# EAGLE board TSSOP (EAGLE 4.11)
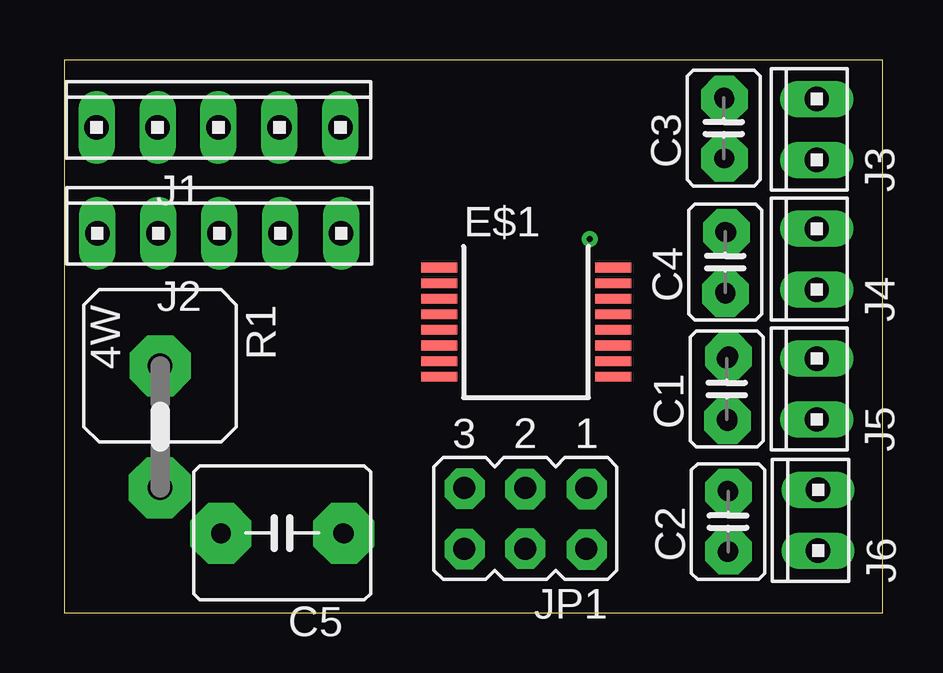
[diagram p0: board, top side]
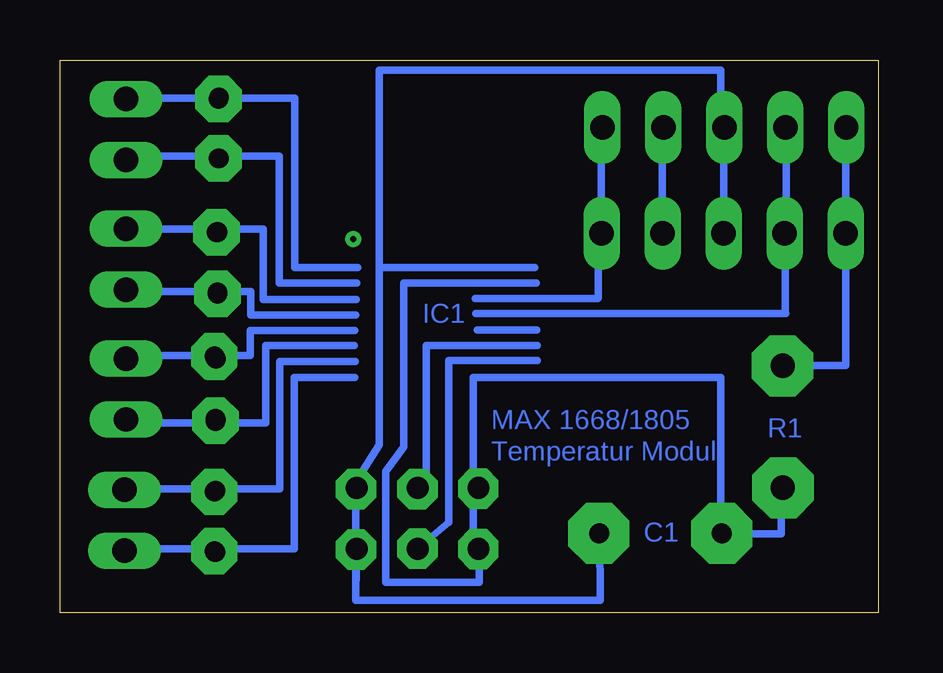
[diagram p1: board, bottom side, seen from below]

Size 34.1 x 23.04 mm. Coordinates in mm from the lower left corner, seen from the top.
Outline: 0,0 34.1,0 34.1,23.04 0,23.04 0,0
Copper layers (1*16): Top 0.035mm / dielectric 1.5mm / Bottom 0.035mm
Design rules "default": minimum track width 10mil, minimum drill 24mil, track to track 8mil, track to pad 8mil, pad to pad 8mil, via to via 8mil, smd to smd 8mil, copper to edge 40mil, drill to drill 8mil, minimum pad ring 10mil, minimum via ring 8mil, stop-mask expansion 4mil, vias tented up to drill 0mil, thermal gap 10mil

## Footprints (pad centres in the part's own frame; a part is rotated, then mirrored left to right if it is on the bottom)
C2.5-3 = drill 0.813 pad 1.6 octagon: 1 -1.27,0; 2 1.27,0
C5B5.5 = drill 0.813 pad 1.6 octagon: 1 -2.54,0; 2 2.54,0
SSOP16 = smd 0.4 x 1.5: 1 -2.275,-3.625; 2 -1.625,-3.625; 3 -0.975,-3.625; 4 -0.325,-3.625; 5 0.325,-3.625; 6 0.975,-3.625; 7 1.625,-3.625; 8 2.275,-3.625; 9 2.275,3.625; 10 1.625,3.625; 11 0.975,3.625; 12 0.325,3.625; 13 -0.325,3.625; 14 -0.975,3.625; 15 -1.625,3.625; 16 -2.275,3.625
10X05MTA = drill 1.016 long: 1 5.08,0; 2 2.54,0; 3 0,0; 4 -2.54,0; 5 -5.08,0
10X02MTA = drill 1.016 long: 1 1.27,0; 2 -1.27,0
JP3Q = drill 0.914 octagon: 1 -2.54,-1.27; 2 -2.54,1.27; 3 0,-1.27; 4 0,1.27; 5 2.54,-1.27; 6 2.54,1.27
KH206-8R = drill 1.016 pad 2.54 octagon: 1 -2.54,0; 2 2.54,0

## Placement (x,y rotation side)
C1  [C2.5-3]  27.59,9.32 90 top
C2  [C2.5-3]  27.65,3.79 90 top
C3  [C2.5-3]  27.48,20.2 90 top
C4  [C2.5-3]  27.53,14.62 90 top
C5  [C5B5.5]  9.08,3.32 180 top
E$1  [SSOP16]  19.24,12.11 270 top
J1  [10X05MTA]  6.42,20.23 0 top
J2  [10X05MTA]  6.45,15.81 0 top
J3  [10X02MTA]  31.35,20.14 90 top
J4  [10X02MTA]  31.35,14.73 90 top
J5  [10X02MTA]  31.35,9.32 90 top
J6  [10X02MTA]  31.41,3.85 90 top
JP1  [JP3Q]  19.2,3.92 180 top
R1  [KH206-8R]  3.99,7.75 270 top

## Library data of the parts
C1-C5 = capacitor-wima
E$1 = maxim
J1-J6 = con-amp
JP1 = jumper
R1 = resistor-power

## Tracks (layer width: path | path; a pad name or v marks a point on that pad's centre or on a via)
S$1
  Bottom 0.305: 21.71,14.39 24.32,14.39 24.32,21.45 31.23,21.45 31.23,21.37
S$2  (via drill 0.25)
  other vias: 21.89,15.58
S$3
  Bottom 0.305: 21.74,13.73 24.97,13.73 24.97,19.03 30.76,19.03 30.76,19.18
S$4
  Bottom 0.305: 21.75,13.05 25.64,13.05 25.64,15.99 31.28,15.99 31.28,15.82
S$5
  Bottom 0.305: 21.78,12.4 26.16,12.4 26.16,13.38 31.08,13.38 31.08,13.48
S$6
  Bottom 0.305: 21.82,11.77 26.18,11.77 26.18,10.71 30.98,10.71 30.98,10.66
S$7
  Bottom 0.305: 21.85,11.14 25.53,11.14 25.53,7.9 31.16,7.9 31.16,7.83
S$8
  Bottom 0.305: 21.81,10.46 24.95,10.46 24.95,5.16 31.13,5.16
S$9
  Bottom 0.305: 21.82,9.81 24.35,9.81 24.35,2.65 31.41,2.65 31.41,2.47
S$10
  Bottom 0.305: 15,9.81 16.88,9.81 16.88,2.63
S$11
  Bottom 0.305: 14.32,14.38 16.96,14.38 20.8,14.38 | 6.61,22.62 20.8,22.62 20.8,14.38 | 20.8,14.38 | 20.8,14.38 20.8,7 21.78,5.44 21.76,1.37
S$12
  Bottom 0.305: 1.36,14.94 1.36,10.3 3.31,10.3
S$13
  Bottom 0.305: 15.84,9.8 6.56,9.8 6.56,3.29
S$14
  Bottom 0.305: 14.21,10.51 17.91,10.51 17.91,3.76 19.32,2.57
S$15
  Bottom 0.305: 14.23,11.14 18.85,11.14 18.85,5.26
S$17
  Bottom 0.305: 21.78,2.42 21.78,0.5 11.6,0.5 11.6,3.24
S$18
  Bottom 0.305: 6.54,3.28 4.05,3.28 4.05,5.18
S$19
  Bottom 0.305: 11.67,13.11 11.67,15.04
S$21
  Bottom 0.305: 11.69,13.1 16.8,13.09
S$22
  Bottom 0.305: 3.87,12.47 3.87,14.79
S$23
  Bottom 0.305: 3.87,12.46 16.78,12.46
S$24
  Bottom 0.305: 16.72,11.79 14.25,11.79
S$25
  Bottom 0.305: 6.58,22.62 6.58,21.18
S$26
  Bottom 0.305: 6.45,19.25 6.45,16.91 6.5,16.91
S$27
  Bottom 0.305: 9,19.28 9,16.82 8.98,16.82
S$28
  Bottom 0.305: 11.55,19.3 11.55,16.79 11.56,16.79
S$29
  Bottom 0.305: 3.85,19.35 3.85,16.96 3.83,16.96
S$30
  Bottom 0.305: 1.36,19.3 1.36,16.89 1.37,16.89
S$32  (via drill 0.81 pad 2.54)
  other vias: 6.52,3.3
S$33  (via drill 0.81 pad 2.54)
  other vias: 11.65,3.3
S$34  (via drill 0.81 pad 2.54)
  other vias: 3.96,5.21
S$35  (via drill 0.81 pad 2.54)
  other vias: 4,10.29
S$36  (via drill 0.81 pad 1.78, 0.81 pad 1.93)
  other vias: 27.63,2.51 27.67,2.56
S$37  (via drill 0.81 pad 1.78, 0.81 pad 1.93)
  other vias: 27.63,5.08 27.67,5.03
S$38  (via drill 0.81 pad 1.78, 0.81 pad 1.93)
  other vias: 27.63,8.07 27.63,7.99
S$39  (via drill 0.81 pad 1.78, 0.81 pad 1.93)
  other vias: 27.63,10.59 27.67,10.68
S$40  (via drill 0.81 pad 1.78, 0.81 pad 1.93)
  other vias: 27.54,13.33 27.54,13.29
S$41  (via drill 0.81 pad 1.78, 0.81 pad 1.93)
  other vias: 27.54,15.85 27.58,15.85
S$42  (via drill 0.81 pad 1.93)
  other vias: 27.5,21.41
S$43  (via drill 0.81 pad 1.93)
  other vias: 27.5,18.94
S$44  (via drill 0.81 pad 1.68)
  other vias: 21.77,5.14
S$45  (via drill 0.81 pad 1.68)
  other vias: 21.77,2.63
S$46  (via drill 0.81 pad 1.68)
  other vias: 19.21,2.67
S$47  (via drill 0.81 pad 1.68)
  other vias: 19.21,5.14
S$48  (via drill 0.81 pad 1.68)
  other vias: 16.68,5.16
S$49  (via drill 0.81 pad 1.68)
  other vias: 16.68,2.65
S$50
  Bottom 0.305: 14.27,13.74 19.78,13.74 19.78,6.92 20.52,5.9 20.52,1.26 16.63,1.26 16.63,2.08

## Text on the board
Bottom: IC1 | R1 | MAX 1668/1805 | Temperatur Modul | C1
